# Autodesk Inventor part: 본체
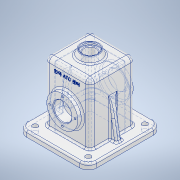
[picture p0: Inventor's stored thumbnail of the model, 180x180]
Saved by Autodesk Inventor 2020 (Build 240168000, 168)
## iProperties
Created: 2022-11
Part Number: 본체
Material: 알루미늄 6061
Document SubType Name: Modeling
Designer: USER
Density: 2.7 g/cm^3
Appearance: 알루미늄 - 평지
Author: USER
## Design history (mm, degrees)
sketch "스케치1"
  geometry: L1 (62, -65)-(-62, -65); L2 (-62, -65)-(-62, 65); L3 (-62, 65)-(62, 65); L4 (62, 65)-(62, -65); L5 (62, -65)-(-62, 65); L6 (-62, -65)-(62, 65); 1 further point
  constraints: 12 end point, 2 midpoint, 2 parallel, 1 horizontal, 1 perpendicular
  dimensions: "d0" = 124 distance of L2.end L3.end; "d1" = 130 distance of L1.end L2.end
extrude "돌출1" new body sketch "스케치1" distance "d2" = 10; taper "d3" = 0 deg
fillet "모깎기1" dims "d4" = 15
sketch "스케치2"
  geometry: L1 (-40, 40)-(40, 40); L2 (40, 40)-(40, -40); L3 (40, -40)-(-40, -40); L4 (-40, -40)-(-40, 40); L5 (-40, 40)-(40, -40); L6 (40, 40)-(-40, -40); 1 further point
  constraints: 12 end point, 2 midpoint, 2 parallel, 1 horizontal, 1 perpendicular
  dimensions: "d5" = 80 distance of L2.end L3.end; "d6" = 80 distance of L1.end L2.end
extrude "돌출2" join sketch "스케치2" distance "d7" = 107; taper "d8" = 0 deg
sketch "스케치6"
  geometry: L1 (80, 0)-(0, 0) reference; L2 (40, 0)-(40, 45); C1 r 27.5 at (40, 45); 1 further point
  constraints: 2 end point, 1 centre point, 1 coincident, 1 midpoint, 1 vertical
  dimensions: "d18" = 45 distance of L2.start L2.end; "d19" = 55 diameter of C1
extrude "돌출6" join sketch "스케치6" distance "d20" = 9; taper "d21" = 0 deg
sketch "스케치7"
  geometry: 1 further point
sketch "스케치8"
  geometry: C1 r 27.5 at (0, 0) reference; C2 r 16 at (0, 0); 1 further point
  constraints: 1 centre point, 1 coincident
  dimensions: "d25" = 32 diameter of C2
extrude "돌출7" cut sketch "스케치8" extent not by distance; stored distance "d26" = 0; taper "d27" = 0 deg
chamfer "모따기2" distance "d28" = 1; stored, may be unused: second distance "d29" = 2, angle "d30" = 45 deg
sketch "스케치9"
  geometry: L1 (117, 40)-(117, -40) reference; L2 (117, 0)-(117, -20); L3 (117, -20)-(127, -16.36); L4 (117, -20)-(136.148, -20); L5 (117, 0)-(127, 0); L6 (127, 0)-(127, -16.36); L7 (117, -40)-(117, 40); L8 (117, 0)-(117, 20); L9 (117, 20)-(127, 16.36); L10 (127, 0)-(127, 16.36); 4 further points
  constraints: 18 end point, 5 symmetric about line, 2 horizontal, 2 point on line, 1 midpoint, 1 perpendicular
revolve "회전1" sketch "스케치9" stored, may be unused: angle "d34" = 90 deg
fillet "모깎기2" dims "d35" = 3
sketch "스케치10"
  geometry: C1 r 14 at (0, 0); 1 further point
  constraints: 1 centre point, 1 coincident
  dimensions: "d36" = 28 diameter of C1
extrude "돌출8" cut sketch "스케치10" distance "d37" = 4; taper "d38" = 0 deg
chamfer "모따기3" distance "d39" = 1; stored, may be unused: second distance "d40" = 2, angle "d41" = 45 deg
sketch "스케치11"
  geometry: C1 r 10.5 at (0, 0); 1 further point
  constraints: 1 centre point, 1 coincident
  dimensions: "d42" = 21 diameter of C1
extrude "돌출9" cut sketch "스케치11" distance "d43" = 32.5; taper "d44" = 0 deg
sketch "스케치12"
  geometry: L1 (32, 32)-(-32, 32); L2 (-32, 32)-(-32, -32); L3 (-32, -32)-(32, -32); L4 (32, -32)-(32, 32); L5 (32, 32)-(-32, -32); L6 (-32, 32)-(32, -32); 1 further point
  constraints: 12 end point, 2 midpoint, 2 parallel, 1 horizontal, 1 perpendicular
  dimensions: "d45" = 64 distance of L3.end L2.end; "d46" = 64 distance of L2.end L1.end
extrude "돌출10" cut sketch "스케치12" distance "d47" = 109; taper "d48" = 0 deg
sketch "스케치13" dims "d49" = 45
  geometry: L1 (0, 0)-(0, 22.5); C1 r 27.5 at (0, 0) reference; C2 r 16 at (0, 0) reference; 2 further points
  constraints: 2 end point, 1 coincident, 1 vertical, 1 vertical alignment, 2 other
hole "구멍1" sketch "스케치13" at (0, 22.5) diameter "d50" = 3.242; stored, may be unused: countersink angle "d54" = 82 deg, drill point angle "d56" = 118 deg; dims "d51" = 8, "d52" = 3.023, "d53" = 2, "d55" = 10
sketch "스케치14"
  geometry: C1 r 4.5 at (-47, 50); A1 r 15 centre (-47, 50) between (-47, 65) and (-62, 50) reference; 1 further point
  constraints: 1 centre point, 1 coincident
  dimensions: "d60" = 9 diameter of C1
extrude "돌출11" cut sketch "스케치14" extent not by distance; stored distance "d61" = 0; taper "d62" = 0 deg
sketch "스케치15"
  geometry: L1 (-62, 10)-(-47, 10); L2 (-62, 10)-(-62, 0); L3 (-62, 10)-(-52, 10); L4 (-52, 10)-(-44.415, 53.017); L5 (-44.415, 53.017)-(-40, 78.055); L6 (-40, 10)-(-40, 117); L7 (-47, 10)-(-40, 10); L8 (-42.5, 0)-(-51.5, 0) reference; 1 further point
  constraints: 14 end point, 2 point on line, 1 parallel
extrude "돌출12" join sketch "스케치15" stored distance "d65" = 10; taper "d66" = 0 deg
fillet "모깎기3" dims "d67" = 3
sketch "스케치16"
  geometry: L1 (47, 10)-(62, 10) reference; L2 (40, 10)-(40, 117) reference; L3 (47, 10)-(62, 10) reference; L4 (62, 10)-(52, 10); L5 (52, 10)-(37.717, 91.001); L6 (52, 10)-(134.251, 10); L7 (47, 10)-(40, 10); 3 further points
  constraints: 8 end point, 2 horizontal, 1 equal length, 1 point on line
  dimensions: "d68" = 10 distance of L1.end L4.end; "d69" = 100 deg angle of L6 L5
extrude "돌출13" join sketch "스케치16" stored distance "d70" = 10; taper "d71" = 0 deg
fillet "모깎기4" dims "d72" = 3
fillet "모깎기5" dims "d73" = 8
fillet "모깎기6" dims "d74" = 8
fillet "모깎기7" dims "d75" = 3
fillet "모깎기8" dims "d76" = 3
fillet "모깎기9" dims "d77" = 3
sketch "스케치17"
  geometry: L1 (8.314, -4)-(54.433, -4); L2 (54.433, -4)-(54.433, -10.004); L3 (54.433, -10.004)-(8.314, -10.004); L4 (8.314, -10.004)-(8.314, -4); L5 (72, -96)-(72, 0) reference; L6 (48.36, 18)-(15.64, 18) reference; 2 further points
  constraints: 2 other
  dimensions: "d80" = 40 distance from line of L5 point (32, -7); "d81" = 25 distance from line of L6 point (32, -7); "d82" = 3 distance from line of L1 point (32, -7); "d83" = 6.00407 distance between parallel lines of L3 L1; "d84" = 23.68594 distance from line of L4 point (32, -7); "d85" = 46.1194 distance between parallel lines of L2 L4
feature "엠보싱1" sketch "스케치17" dims "d86" = 0.5, "d87" = 0
chamfer "모따기4" distance "d88" = 1; stored, may be unused: second distance "d89" = 2, angle "d90" = 45 deg
node "솔리드1"
mirror "미러1"
pattern_circular "원형 패턴1" dims angle "d58" = 360 deg
mirror "미러2"
mirror "미러3"
mirror "미러4"
node "투영된 루프1"
feature "A9D066F2-1C7D-4E18-AEED-F7BC21143FA4" dims "d50" = 3.242, "d51" = 8, "d52" = 3.023, "d53" = 2, "d54" = 82 deg, "d55" = 10, "d56" = 118 deg
